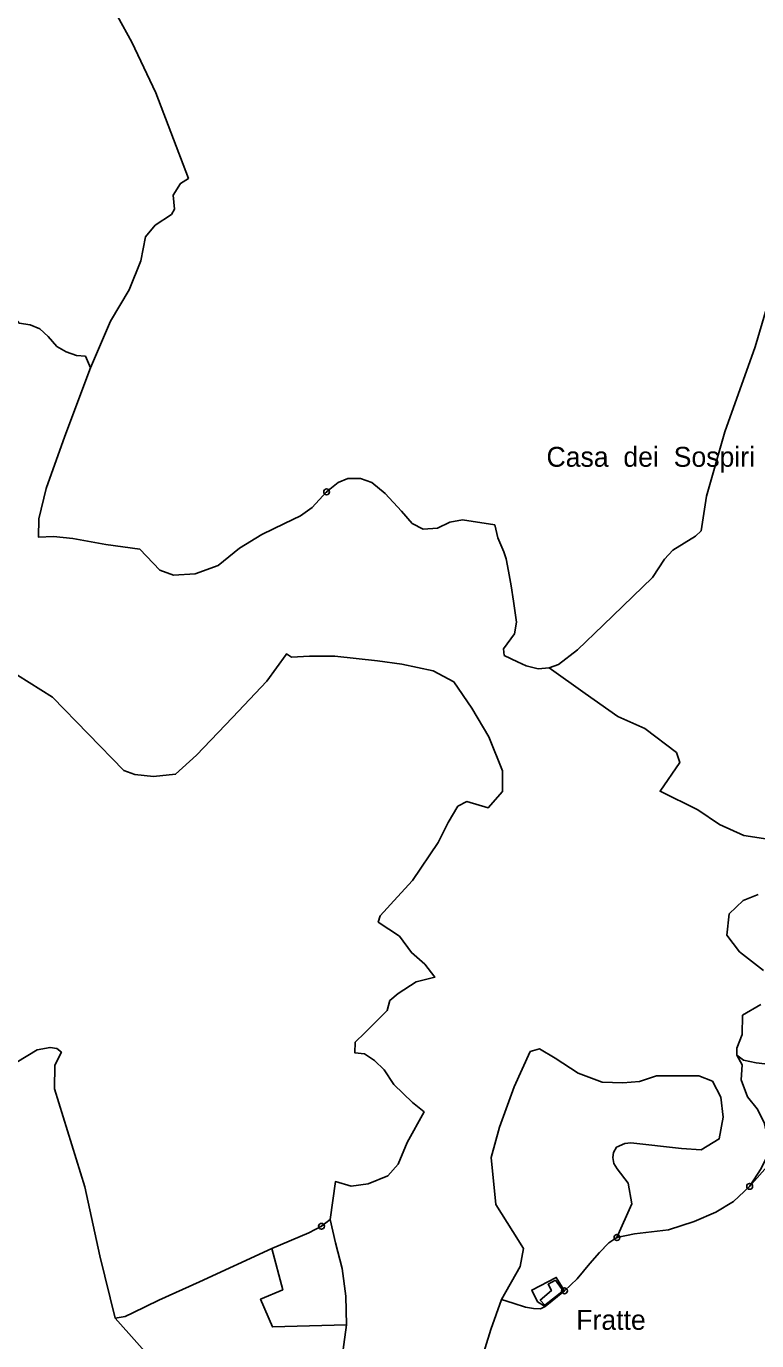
# Model space of a CAD drawing. Extents: x 645880 to 658994, y 884400 to 894744.
# Drawn here: x 655899 to 656523, y 892132 to 893255 of the extents above; entities that cross this region are included whole.
import ezdxf
from ezdxf.enums import TextEntityAlignment as Align

# ---------------------------------------------------------------- set-up
doc = ezdxf.new("R2010")
doc.units = 0
doc.header["$LTSCALE"] = 10
doc.header["$PDMODE"] = 32
doc.header["$PDSIZE"] = 5
for name, color, linetype, lineweight in [('16', 7, 'Continuous', 25), ('17', 7, 'Continuous', 25), ('18', 7, 'Continuous', 25), ('32', 7, 'Continuous', 25), ('4', 7, 'Continuous', 25)]:
    doc.layers.add(name, color=color, linetype=linetype, lineweight=lineweight)
doc.layers.add('60', color=7, linetype='Continuous')

msp = doc.modelspace()

# ---------------------------------------------------------------- linework, layer by layer
at = {"layer": '16'}
msp.add_line((656358.92, 892175.07), (656342.45, 892161.69), dxfattribs=at)
for points in [[(655964.9, 893286.46), (655989.13, 893241.94), (656009.76, 893198.42), (656037.6, 893125.39), (656030.91, 893121.14), (656024.72, 893111.14), (656025.75, 893099.14), (656023.17, 893094.63), (656009.25, 893085.63), (656001, 893075.63), (655996.88, 893055.12), (655987.08, 893030.11), (655971.09, 893003.6), (655954.08, 892963.58), (655932.13, 892905.15), (655916.14, 892860.63), (655909.95, 892834.62), (655909.63, 892818.89), (655922.3, 892819.44), (655938.84, 892817.79)], [(656538.96, 893039.38), (656521.77, 892981.53), (656495.98, 892908.81), (656480.35, 892854.08), (656475.67, 892824.37), (656470.98, 892819.68), (656451.44, 892807.96), (656444.41, 892800.14), (656434.25, 892784.5), (656392.06, 892743.84)], [(656392.06, 892743.84), (656434.25, 892784.5), (656444.41, 892800.14), (656451.44, 892807.96), (656470.98, 892819.68), (656475.67, 892824.37), (656480.35, 892854.08), (656495.98, 892908.81), (656521.77, 892981.53), (656538.96, 893039.38)], [(656155.67, 892857.66), (656165.47, 892865.66), (656173.72, 892869.16), (656184.55, 892869.16), (656194.34, 892865.66), (656205.69, 892856.16), (656219.61, 892841.15), (656228.89, 892830.64), (656238.17, 892825.64), (656250.55, 892826.64), (656260.86, 892831.65), (656271.69, 892833.65), (656299.32, 892829.4), (656301.9, 892818.4), (656307.05, 892806.39), (656309.11, 892800.39), (656311.18, 892789.89), (656313.24, 892777.38), (656315.3, 892764.38), (656317.88, 892746.38), (656316.33, 892736.37), (656306.83, 892723.57), (656307.42, 892717.94), (656318.91, 892712.37), (656326.13, 892708.87), (656336.44, 892706.36), (656345.72, 892707.37)], [(655938.84, 892817.79), (655967.19, 892812.61), (655996.06, 892808.61), (656013.08, 892790.6), (656024.94, 892786.6), (656043.5, 892787.6), (656063.1, 892794.6), (656081.14, 892809.61), (656100.22, 892821.11), (656119.82, 892830.62), (656133.5, 892837.15), (656143.3, 892844.15), (656155.67, 892857.66)], [(656246.73, 892704.86), (656219.92, 892710.37), (656199.3, 892713.37), (656162.69, 892717.37), (656141.04, 892717.37), (656125.57, 892716.37), (656121.36, 892719.13), (656121.12, 892718.66), (656104.57, 892695.85), (656075.19, 892664.84), (656044.38, 892632.77), (656026.62, 892616.45), (656007.72, 892614.56), (655991.84, 892616.22), (655982.38, 892619.71), (655921.47, 892682.13), (655881.54, 892707.33), (655855.43, 892732.01), (655839.07, 892755.46), (655833.01, 892783.59), (655829.33, 892807.49)], [(656392.06, 892743.84), (656370.17, 892722.74), (656353.76, 892710.23), (656345.72, 892707.37), (656376.65, 892685.36), (656404.49, 892665.85), (656427.69, 892655.35), (656454.5, 892634.85), (656457.6, 892626.34), (656440.58, 892601.84), (656472.89, 892586.07), (656491.45, 892573.56), (656512.07, 892564.06), (656532.7, 892561.06)], [(656345.72, 892707.37), (656353.76, 892710.23), (656370.17, 892722.74), (656392.06, 892743.84)], [(656151.26, 892230.2), (656158.74, 892235.97), (656163.21, 892268.36), (656176.62, 892264.36), (656191.05, 892266.36), (656208.07, 892273.36), (656216.83, 892283.36), (656224.56, 892301.87), (656239, 892327.87), (656229.2, 892335.88), (656213.22, 892351.38), (656204.97, 892363.88), (656196.72, 892371.89), (656187.96, 892377.39), (656179.71, 892378.39), (656180.21, 892387.53), (656188.46, 892395.53), (656207.54, 892414.54), (656209.6, 892423.04), (656216.82, 892429.04), (656232.29, 892439.04), (656248.27, 892443.04), (656239.5, 892454.05), (656228.16, 892464.05), (656217.85, 892478.05), (656199.81, 892490.06), (656201.35, 892495.56), (656216.3, 892511.56), (656229.19, 892525.57), (656250.85, 892558.07), (656259.61, 892575.08), (656267.86, 892589.08), (656275.59, 892593.08), (656293.64, 892587.58), (656306.01, 892601.59), (656306.02, 892619.34), (656294.16, 892648.35), (656279.73, 892672.86), (656264.26, 892695.36), (656246.73, 892704.86)], [(656524.45, 892513.55), (656511.56, 892508.55), (656499.7, 892497.04), (656497.64, 892479.04), (656508.33, 892464.77), (656528.96, 892448.77)], [(656526.79, 892419.68), (656511.09, 892410.53), (656510.85, 892394.11), (656506.27, 892382.25), (656506.27, 892376.25), (656511.94, 892372.25), (656522.77, 892369.74), (656535, 892368.3)], [(655891.08, 892370.39), (655908.34, 892380.98), (655919.47, 892383.03), (655925.23, 892382.1), (655929.17, 892378.91), (655923.37, 892367.98), (655923.19, 892347.74), (655949.13, 892263.8), (655962, 892204.93)], [(656403.22, 892297.65), (656410.57, 892300.86), (656415.46, 892301.61), (656458.95, 892296.71), (656475.71, 892295.58), (656491.15, 892304.83), (656494.49, 892323.31), (656492.54, 892340.55), (656485.32, 892354.17), (656473.62, 892358.84), (656437.53, 892358.84), (656423.1, 892353.84), (656408.66, 892352.84), (656391.18, 892353.42), (656370.47, 892361.14), (656350.89, 892373.95), (656337.52, 892381.67), (656329.61, 892379.41), (656315.87, 892349.27), (656303.49, 892314.83), (656296.28, 892288.82), (656300.4, 892248.82), (656314.84, 892225.81), (656323.78, 892211.18), (656321.02, 892195.8), (656305.18, 892167.58), (656314.98, 892164.64)], [(656400.21, 892288.99), (656400.78, 892293.13), (656403.22, 892297.65)], [(656638.64, 892063.31), (656630.43, 892068.88), (656619.64, 892077.67), (656605.34, 892093.73), (656584.77, 892117.32), (656572.73, 892135.9), (656566.96, 892139.91), (656557.43, 892148.44), (656549.16, 892167.02), (656542.88, 892179.82), (656543.89, 892188.6), (656547.15, 892199.64), (656557.68, 892214.95), (656563.45, 892223.48), (656567.21, 892231.26), (656569.22, 892241.55), (656567.47, 892256.36), (656563.45, 892265.14), (656553.17, 892276.44), (656547.15, 892284.47), (656541.85, 892290.3), (656536.7, 892286.3), (656527.93, 892276.29), (656517.11, 892264.29)], [(656396.37, 892215.49), (656396.9, 892216.02), (656403.75, 892220.53), (656416.59, 892249.43), (656413.39, 892267.14), (656403.79, 892279.38)], [(656403.79, 892279.38), (656401.15, 892283.71), (656400.21, 892288.99)], [(656517.11, 892264.29), (656503.19, 892251.29), (656488.23, 892242.28), (656469.67, 892234.28), (656447.77, 892227.11), (656418.86, 892223.82), (656403.75, 892220.53)], [(655983.63, 892153.18), (655990.01, 892156.11), (656012.47, 892167.06), (656046.95, 892182.65), (656108.94, 892211.29), (656140.46, 892224.72), (656151.26, 892230.2)], [(656403.75, 892220.53), (656396.9, 892216.02), (656388.69, 892207.81), (656380.67, 892198.45), (656369.78, 892185.27), (656358.92, 892175.07)], [(656380.67, 892198.45), (656388.69, 892207.81), (656396.37, 892215.49)], [(655962, 892204.93), (655975.1, 892151.68), (655983.63, 892153.18)], [(656358.92, 892175.07), (656369.78, 892185.27), (656380.67, 892198.45)], [(656314.98, 892164.64), (656325.48, 892161.2), (656332.55, 892160.05), (656338.47, 892159.67), (656342.45, 892161.69), (656335.81, 892165.77), (656330.97, 892175.67), (656351.9, 892186.55), (656358.92, 892175.07)], [(656342.45, 892161.69), (656338.47, 892159.67), (656332.55, 892160.05), (656325.48, 892161.2), (656314.98, 892164.64), (656305.18, 892167.58), (656295.98, 892141.92), (656286.31, 892110.77), (656278.25, 892100.48)]]:
    msp.add_lwpolyline(points, dxfattribs=at)
for p in [(656155.67, 892857.66), (656517.11, 892264.29), (656151.26, 892230.2), (656403.75, 892220.53), (656358.92, 892175.07)]:
    msp.add_point(p, dxfattribs=at)
at = {"layer": '17'}
for points in [[(656009.73, 892112.7), (655975.1, 892151.68), (655962, 892204.93), (655949.13, 892263.8), (655923.19, 892347.74), (655923.37, 892367.98), (655929.17, 892378.91), (655925.23, 892382.1), (655919.47, 892383.03), (655908.34, 892380.98), (655891.08, 892370.39)], [(656164.31, 892084.95), (656172.63, 892145.91), (656109.37, 892144.22), (656099.31, 892167.83), (656118.25, 892175.9), (656108.94, 892211.29), (656046.95, 892182.65), (656012.47, 892167.06), (655990.01, 892156.11), (655983.63, 892153.18), (655975.1, 892151.68), (656009.73, 892112.7)]]:
    msp.add_lwpolyline(points, dxfattribs=at)
at = {"layer": '18'}
msp.add_line((656511.09, 892410.53), (656510.85, 892394.11), dxfattribs=at)
for points in [[(655971.09, 893003.6), (655987.08, 893030.11), (655996.88, 893055.12), (656001, 893075.63), (656009.25, 893085.63), (656023.17, 893094.63), (656025.75, 893099.14), (656024.72, 893111.14), (656030.91, 893121.14), (656037.6, 893125.39), (656009.76, 893198.42), (655989.13, 893241.94), (655964.9, 893286.46)], [(655888.55, 893007.47), (655892.94, 893001.88), (655902.52, 893000.35), (655910.57, 892996.9), (655917.86, 892990.38), (655925.14, 892981.94), (655933.19, 892977.34), (655942, 892974.27), (655949.67, 892973.5), (655954.08, 892963.58), (655971.09, 893003.6)], [(655892.94, 893001.88), (655902.52, 893000.35), (655910.57, 892996.9), (655917.86, 892990.38), (655925.14, 892981.94), (655933.19, 892977.34), (655942, 892974.27), (655949.67, 892973.5), (655954.08, 892963.58), (655932.13, 892905.15), (655916.14, 892860.63), (655909.95, 892834.62), (655909.63, 892818.89), (655922.3, 892819.44), (655938.84, 892817.79), (655967.19, 892812.61), (655996.06, 892808.61), (656013.08, 892790.6), (656024.94, 892786.6), (656043.5, 892787.6), (656063.1, 892794.6), (656081.14, 892809.61), (656100.22, 892821.11), (656119.82, 892830.62), (656133.5, 892837.15), (656143.3, 892844.15), (656155.67, 892857.66), (656165.47, 892865.66), (656173.72, 892869.16), (656184.55, 892869.16), (656194.34, 892865.66), (656205.69, 892856.16), (656219.61, 892841.15), (656228.89, 892830.64), (656238.17, 892825.64), (656250.55, 892826.64), (656260.86, 892831.65), (656271.69, 892833.65), (656299.32, 892829.4)], [(656299.32, 892829.4), (656301.9, 892818.4), (656307.05, 892806.39), (656309.11, 892800.39), (656311.18, 892789.89), (656313.24, 892777.38), (656315.3, 892764.38), (656317.88, 892746.38), (656316.33, 892736.37), (656306.83, 892723.57), (656307.42, 892717.94), (656318.91, 892712.37), (656326.13, 892708.87), (656336.44, 892706.36), (656345.72, 892707.37), (656376.65, 892685.36), (656404.49, 892665.85), (656427.69, 892655.35), (656454.5, 892634.85), (656457.6, 892626.34), (656440.58, 892601.84), (656472.89, 892586.07), (656491.45, 892573.56), (656512.07, 892564.06), (656532.7, 892561.06)], [(656188.46, 892395.53), (656207.54, 892414.54), (656209.6, 892423.04), (656216.82, 892429.04), (656232.29, 892439.04), (656248.27, 892443.04), (656239.5, 892454.05), (656228.16, 892464.05), (656217.85, 892478.05), (656199.81, 892490.06), (656201.35, 892495.56), (656216.3, 892511.56), (656229.19, 892525.57), (656250.85, 892558.07), (656259.61, 892575.08), (656267.86, 892589.08), (656275.59, 892593.08), (656293.64, 892587.58), (656306.01, 892601.59), (656306.02, 892619.34), (656294.16, 892648.35), (656279.73, 892672.86), (656264.26, 892695.36), (656246.73, 892704.86), (656219.92, 892710.37), (656199.3, 892713.37), (656162.69, 892717.37), (656141.04, 892717.37), (656125.57, 892716.37), (656121.36, 892719.13), (656121.12, 892718.66), (656104.57, 892695.85), (656075.19, 892664.84), (656044.38, 892632.77), (656026.62, 892616.45), (656007.72, 892614.56), (655991.84, 892616.22), (655982.38, 892619.71), (655921.47, 892682.13), (655881.54, 892707.33)], [(656524.45, 892513.55), (656511.56, 892508.55), (656499.7, 892497.04), (656497.64, 892479.04), (656508.33, 892464.77), (656528.96, 892448.77)], [(656526.79, 892419.68), (656511.09, 892410.53)], [(656572.04, 892405.37), (656569.46, 892390.59), (656559.61, 892372.29), (656550.07, 892364.91), (656535, 892368.3), (656522.77, 892369.74), (656511.94, 892372.25), (656506.27, 892376.25)], [(656164.31, 892084.95), (656172.63, 892145.91), (656172.12, 892170.61), (656169.03, 892194.06), (656163.37, 892216.01), (656158.74, 892235.97), (656163.21, 892268.36), (656176.62, 892264.36), (656191.05, 892266.36), (656208.07, 892273.36), (656216.83, 892283.36), (656224.56, 892301.87), (656239, 892327.87), (656229.2, 892335.88), (656213.22, 892351.38), (656204.97, 892363.88), (656196.72, 892371.89), (656187.96, 892377.39), (656179.71, 892378.39), (656180.21, 892387.53), (656188.46, 892395.53)], [(656510.85, 892394.11), (656506.27, 892382.25), (656506.27, 892376.25)], [(656403.22, 892297.65), (656410.57, 892300.86), (656415.46, 892301.61), (656458.95, 892296.71), (656475.71, 892295.58), (656491.15, 892304.83), (656494.49, 892323.31), (656492.54, 892340.55), (656485.32, 892354.17), (656473.62, 892358.84), (656437.53, 892358.84), (656423.1, 892353.84), (656408.66, 892352.84), (656391.18, 892353.42), (656370.47, 892361.14), (656350.89, 892373.95), (656337.52, 892381.67), (656329.61, 892379.41), (656315.87, 892349.27), (656303.49, 892314.83), (656296.28, 892288.82), (656300.4, 892248.82), (656314.84, 892225.81), (656323.78, 892211.18), (656321.02, 892195.8), (656305.18, 892167.58), (656295.98, 892141.92), (656286.31, 892110.77)], [(656506.27, 892376.25), (656510.85, 892368.07), (656509.92, 892355.4), (656515.31, 892340.85), (656523.66, 892330.54), (656529.49, 892318.86), (656532.27, 892306.35), (656532.55, 892291.34), (656526.99, 892279.67), (656517.11, 892264.29), (656503.19, 892251.29), (656488.23, 892242.28), (656469.67, 892234.28), (656447.77, 892227.11), (656418.86, 892223.82), (656403.75, 892220.53), (656416.59, 892249.43), (656413.39, 892267.14), (656403.79, 892279.38)], [(656506.27, 892376.25), (656510.85, 892368.07), (656509.92, 892355.4), (656515.31, 892340.85), (656523.66, 892330.54), (656529.49, 892318.86), (656532.27, 892306.35), (656532.55, 892291.34), (656526.99, 892279.67), (656517.11, 892264.29), (656527.93, 892276.29), (656536.7, 892286.3), (656541.85, 892290.3), (656552.68, 892294.8), (656569.18, 892296.8), (656582.58, 892295.3), (656603.2, 892286.3), (656627.44, 892270.29), (656644.97, 892248.29)], [(656400.21, 892288.99), (656400.78, 892293.13), (656403.22, 892297.65)], [(656403.79, 892279.38), (656401.15, 892283.71), (656400.21, 892288.99)]]:
    msp.add_lwpolyline(points, dxfattribs=at)
at = {"layer": '32'}
msp.add_lwpolyline([(656099.31, 892167.83), (656109.37, 892144.22), (656172.63, 892145.91), (656172.12, 892170.61), (656169.03, 892194.06), (656163.37, 892216.01), (656158.74, 892235.97), (656151.26, 892230.2), (656140.46, 892224.72), (656108.94, 892211.29), (656118.25, 892175.9)], close=True, dxfattribs=at)
at = {"layer": '4'}
for points in [[(656330.96, 892175.67), (656351.89, 892186.55), (656358.91, 892175.07), (656342.44, 892161.69), (656335.8, 892165.77)], [(656351.27, 892184.03), (656344.88, 892180.64), (656347.75, 892175.29), (656338.23, 892167.21), (656342.01, 892162.7), (656357.73, 892175.03)]]:
    msp.add_lwpolyline(points, close=True, dxfattribs=at)

# ---------------------------------------------------------------- texts
at = {"layer": '60'}
for s, p in [('Casa  dei  Sospiri', (656432.62, 892879.07)), ('Fratte', (656398.65, 892141.74))]:
    msp.add_text(s, height=17, dxfattribs=at).set_placement(p, align=Align.CENTER)

doc.saveas('drawing.dxf')
